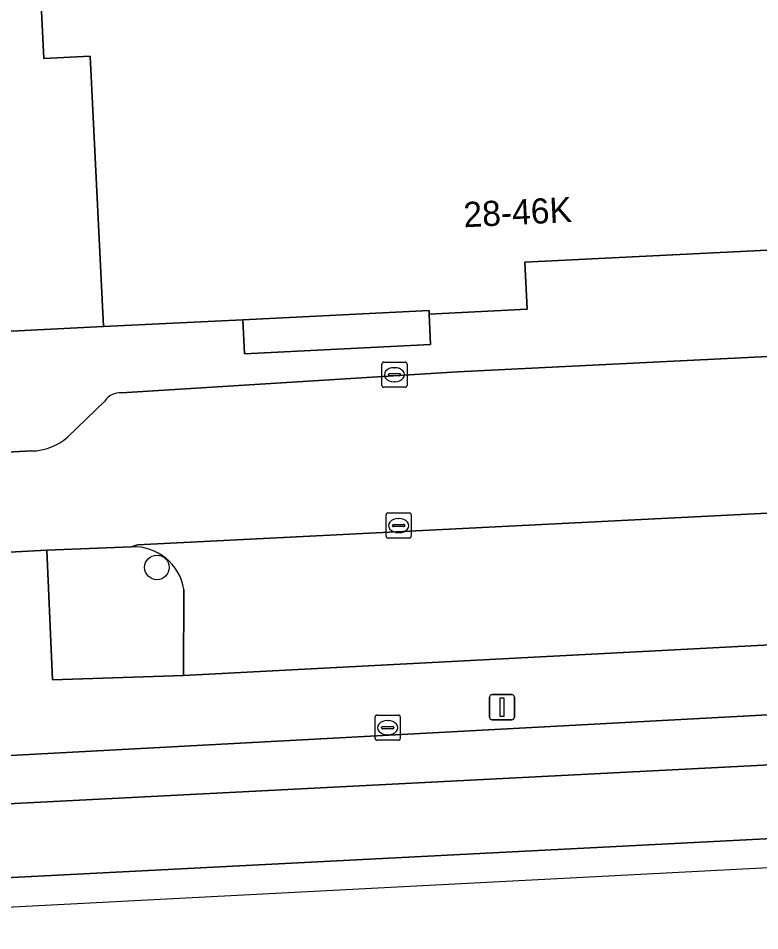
# Model space of a CAD drawing. Extents: x 161084 to 161928, y 385354 to 386522.
# Drawn here: x 161404.59 to 161434.06, y 385358.07 to 385394.35 of the extents above; entities that cross this region are included whole.
import ezdxf

# ---------------------------------------------------------------- set-up
doc = ezdxf.new("R2010")
doc.units = 0
for name, color, linetype in [('IMGEO_Berm_groen', 7, 'Continuous'), ('IMGEO_Boom', 7, 'Continuous'), ('IMGEO_Erf', 7, 'Continuous'), ('IMGEO_Kolk', 7, 'Continuous'), ('IMGEO_Lichtmast', 7, 'Continuous'), ('IMGEO_Pand', 7, 'Continuous'), ('IMGEO_Pand_nummerreeks', 7, 'Continuous'), ('IMGEO_Parkeervlak_open', 7, 'Continuous'), ('IMGEO_Rijbaan_lokaal_gesloten', 7, 'Continuous'), ('IMGEO_Rijbaan_lokaal_open', 7, 'Continuous'), ('IMGEO_Voetpad_open', 7, 'Continuous')]:
    doc.layers.add(name, color=color, linetype=linetype)

msp = doc.modelspace()

# ---------------------------------------------------------------- linework, layer by layer
at = {"layer": 'IMGEO_Berm_groen'}
msp.add_lwpolyline([(161409.084, 385373.337), (161405.722, 385373.199), (161405.948, 385368.052), (161411.152, 385368.227), (161411.169, 385371.645)], dxfattribs=at)
msp.add_arc((161409.17, 385371.312), 2.027, 9.4523, 92.4283, dxfattribs=at)
at = {"layer": 'IMGEO_Boom'}
msp.add_circle((161410.097, 385372.519), 0.489, dxfattribs=at)
at = {"layer": 'IMGEO_Erf'}
msp.add_lwpolyline([(161407.443, 385392.844), (161405.607, 385392.753), (161405.035, 385404.251), (161400.922, 385404.035), (161400.936, 385403.637), (161401.439, 385392.564), (161401.928, 385381.791), (161407.978, 385382.092)], close=True, dxfattribs=at)
at = {"layer": 'IMGEO_Kolk'}
for p, q in [((161419.038, 385379.753), (161419.038, 385380.605)), ((161419.113, 385380.679), (161419.965, 385380.679)), ((161419.526, 385380.459), (161419.551, 385380.459)), ((161420.039, 385380.605), (161420.039, 385379.753)), ((161419.297, 385380.173), (161419.297, 385380.185)), ((161419.735, 385380.136), (161419.337, 385380.136)), ((161419.34, 385380.222), (161419.738, 385380.222)), ((161419.781, 385380.185), (161419.781, 385380.173)), ((161419.965, 385379.679), (161419.113, 385379.679)), ((161419.549, 385379.899), (161419.524, 385379.899)), ((161419.205, 385373.756), (161419.205, 385374.608)), ((161419.28, 385374.682), (161420.132, 385374.682)), ((161420.206, 385374.608), (161420.206, 385373.756)), ((161419.464, 385374.176), (161419.464, 385374.188)), ((161419.507, 385374.225), (161419.905, 385374.225)), ((161419.693, 385374.462), (161419.718, 385374.462)), ((161419.948, 385374.188), (161419.948, 385374.176)), ((161419.902, 385374.139), (161419.504, 385374.139)), ((161419.716, 385373.902), (161419.691, 385373.902)), ((161420.132, 385373.682), (161419.28, 385373.682)), ((161418.772, 385365.721), (161418.772, 385366.573)), ((161418.847, 385366.647), (161419.699, 385366.647)), ((161419.773, 385366.573), (161419.773, 385365.721)), ((161419.26, 385366.427), (161419.285, 385366.427)), ((161419.031, 385366.141), (161419.031, 385366.153)), ((161419.469, 385366.104), (161419.071, 385366.104)), ((161419.074, 385366.19), (161419.472, 385366.19)), ((161419.283, 385365.867), (161419.258, 385365.867)), ((161419.515, 385366.153), (161419.515, 385366.141)), ((161419.699, 385365.647), (161418.847, 385365.647))]:
    msp.add_line(p, q, dxfattribs=at)
for points in [[(161419.038, 385379.753), (161419.038, 385380.605)], [(161419.113, 385380.679), (161419.965, 385380.679)], [(161420.039, 385380.605), (161420.039, 385379.753)], [(161419.965, 385379.679), (161419.113, 385379.679)], [(161419.205, 385373.756), (161419.205, 385374.608)], [(161419.28, 385374.682), (161420.132, 385374.682)], [(161420.206, 385374.608), (161420.206, 385373.756)], [(161420.132, 385373.682), (161419.28, 385373.682)], [(161418.772, 385365.721), (161418.772, 385366.573)], [(161418.847, 385366.647), (161419.699, 385366.647)], [(161419.773, 385366.573), (161419.773, 385365.721)], [(161419.699, 385365.647), (161418.847, 385365.647)]]:
    msp.add_lwpolyline(points, dxfattribs=at)
for centre, radius, start, end in [((161419.115, 385380.603), 0.0765, 91.552, 178.448), ((161419.115, 385380.603), 0.0765, 91.552, 178.448), ((161419.963, 385380.603), 0.0765, 1.552, 88.448), ((161419.963, 385380.603), 0.0765, 1.552, 88.448), ((161419.337, 385380.182), 0.0403, 85.8775, 175.7526), ((161419.334, 385380.172), 0.0366, 178.938, 274.7102), ((161419.738, 385380.179), 0.043, 264.8664, 352.4533), ((161419.742, 385380.184), 0.0386, 1.7309, 96.639), ((161419.115, 385379.755), 0.0765, 181.552, 268.448), ((161419.115, 385379.755), 0.0765, 181.552, 268.448), ((161419.963, 385379.755), 0.0765, 271.552, 358.448), ((161419.963, 385379.755), 0.0765, 271.552, 358.448), ((161419.282, 385374.606), 0.0765, 91.552, 178.448), ((161419.282, 385374.606), 0.0765, 91.552, 178.448), ((161420.13, 385374.606), 0.0765, 1.552, 88.448), ((161420.13, 385374.606), 0.0765, 1.552, 88.448), ((161419.504, 385374.185), 0.0403, 85.8775, 175.7526), ((161419.909, 385374.187), 0.0386, 1.7309, 96.639), ((161419.501, 385374.175), 0.0366, 178.938, 274.7102), ((161419.905, 385374.182), 0.043, 264.8664, 352.4533), ((161419.282, 385373.758), 0.0765, 181.552, 268.448), ((161419.282, 385373.758), 0.0765, 181.552, 268.448), ((161420.13, 385373.758), 0.0765, 271.552, 358.448), ((161420.13, 385373.758), 0.0765, 271.552, 358.448), ((161418.849, 385366.571), 0.0765, 91.552, 178.448), ((161418.849, 385366.571), 0.0765, 91.552, 178.448), ((161419.697, 385366.571), 0.0765, 1.552, 88.448), ((161419.697, 385366.571), 0.0765, 1.552, 88.448), ((161419.071, 385366.15), 0.0403, 85.8775, 175.7526), ((161419.068, 385366.14), 0.0366, 178.938, 274.7102), ((161419.472, 385366.147), 0.043, 264.8664, 352.4533), ((161419.476, 385366.152), 0.0386, 1.7309, 96.639), ((161418.849, 385365.723), 0.0765, 181.552, 268.448), ((161418.849, 385365.723), 0.0765, 181.552, 268.448), ((161419.697, 385365.723), 0.0765, 271.552, 358.448), ((161419.697, 385365.723), 0.0765, 271.552, 358.448)]:
    msp.add_arc(centre, radius, start, end, dxfattribs=at)
for centre, major_axis, ratio, start_param, end_param in [((161419.525, 385380.179), (-0.387, 0.002), 0.722429, 4.712389, 7.853982), ((161419.55, 385380.179), (-0.39, 0.002), 0.717154, 1.570796, 4.712389), ((161419.692, 385374.182), (-0.387, 0.002), 0.722429, 4.712389, 7.853982), ((161419.717, 385374.182), (-0.39, 0.002), 0.717154, 1.570796, 4.712389), ((161419.259, 385366.147), (-0.387, 0.002), 0.722429, 4.712389, 7.853982), ((161419.284, 385366.147), (-0.39, 0.002), 0.717154, 1.570796, 4.712389)]:
    msp.add_ellipse(centre, major_axis=major_axis, ratio=ratio, start_param=start_param, end_param=end_param, dxfattribs=at)
at = {"layer": 'IMGEO_Lichtmast'}
for p, q in [((161423.317, 385366.56), (161423.317, 385367.36)), ((161423.317, 385367.36), (161423.317, 385366.56)), ((161423.417, 385367.46), (161424.207, 385367.46)), ((161424.207, 385367.46), (161423.417, 385367.46)), ((161424.307, 385367.36), (161424.307, 385366.56)), ((161424.307, 385366.56), (161424.307, 385367.36)), ((161424.207, 385366.46), (161423.417, 385366.46)), ((161423.417, 385366.46), (161424.207, 385366.46))]:
    msp.add_line(p, q, dxfattribs=at)
msp.add_lwpolyline([(161423.737, 385367.335), (161423.887, 385367.335), (161423.887, 385366.585), (161423.737, 385366.585), (161423.737, 385367.335)], dxfattribs=at)
for centre, start, end in [((161423.417, 385367.36), 90, 180), ((161423.417, 385367.36), 90, 180), ((161424.207, 385367.36), 0, 90), ((161424.207, 385367.36), 360, 90), ((161423.417, 385366.56), 180, 270), ((161423.417, 385366.56), 180, 270), ((161424.207, 385366.56), 270, 0), ((161424.207, 385366.56), 270, 0)]:
    msp.add_arc(centre, 0.1, start, end, dxfattribs=at)
at = {"layer": 'IMGEO_Pand'}
msp.add_lwpolyline([(161445.572, 385399.025), (161442.544, 385398.875), (161442.426, 385401.249), (161440.171, 385401.137), (161440.017, 385404.225), (161423.461, 385403.401), (161418.467, 385403.152), (161418.379, 385404.916), (161405.035, 385404.251), (161405.607, 385392.753), (161407.443, 385392.844), (161407.978, 385382.092), (161413.514, 385382.368), (161420.918, 385382.736), (161420.925, 385382.589), (161424.817, 385382.783), (161424.724, 385384.657), (161439.175, 385385.376), (161440.478, 385385.441), (161440.573, 385383.548), (161445.352, 385383.786), (161446.313, 385383.833)], close=True, dxfattribs=at)
at = {"layer": 'IMGEO_Parkeervlak_open'}
for points in [[(161613.107, 385383.789), (161536.651, 385379.888), (161500, 385377.979), (161409.328, 385373.422), (161409.084, 385373.337)], [(161411.169, 385371.645), (161411.152, 385368.227), (161436.244, 385369.529), (161499.966, 385372.793), (161536.947, 385374.696), (161611.734, 385378.546)]]:
    msp.add_lwpolyline(points, dxfattribs=at)
msp.add_arc((161409.17, 385371.312), 2.027, 9.4523, 92.4283, dxfattribs=at)
at = {"layer": 'IMGEO_Rijbaan_lokaal_gesloten'}
for points in [[(161625.701, 385371.623), (161625.454, 385376.07), (161622.465, 385375.567), (161622.181, 385375.572), (161615.993, 385374.116), (161611.842, 385373.703), (161604.686, 385373.29), (161508.768, 385368.474), (161402.097, 385363.009), (161402.264, 385360.078), (161479.217, 385364.029), (161505.666, 385365.356), (161523.978, 385366.275), (161544.274, 385367.294), (161580.676, 385369.12), (161602.822, 385370.279), (161621.627, 385370.918)], [(161402.333, 385358.921), (161450.189, 385361.402), (161611.523, 385369.168), (161621.627, 385370.918), (161602.822, 385370.279), (161580.676, 385369.12), (161544.274, 385367.294), (161523.978, 385366.275), (161505.666, 385365.356), (161479.217, 385364.029), (161402.264, 385360.078)]]:
    msp.add_lwpolyline(points, close=True, dxfattribs=at)
for points in [[(161508.768, 385368.474), (161604.686, 385373.29), (161611.842, 385373.703), (161615.993, 385374.116), (161622.181, 385375.572), (161612.776, 385375.763), (161606.577, 385375.444), (161537.172, 385371.897), (161505.307, 385370.314), (161500.052, 385370.04), (161436.355, 385366.757), (161401.799, 385364.905), (161400.42, 385364.894), (161400.333, 385364.8), (161381.454, 385363.768), (161381.262, 385363.858), (161323.951, 385361)], [(161292.857, 385361.465), (161286.612, 385360.011), (161288.172, 385359.529), (161291.222, 385358.909), (161294.158, 385358.451), (161297.736, 385358.198), (161302.025, 385358.107), (161303.986, 385358.072), (161307.966, 385358.21), (161314.892, 385358.542), (161402.097, 385363.009), (161508.768, 385368.474)]]:
    msp.add_lwpolyline(points, dxfattribs=at)
at = {"layer": 'IMGEO_Rijbaan_lokaal_open'}
for points in [[(161503.842, 385384.114), (161501.355, 385384.05), (161500, 385384.027), (161446.746, 385381.511), (161422.04, 385380.3), (161408.687, 385379.455)], [(161396.971, 385372.736), (161405.722, 385373.199), (161409.084, 385373.337), (161409.328, 385373.422), (161500, 385377.979), (161536.651, 385379.888), (161613.107, 385383.789)], [(161408.022, 385379.129), (161406.548, 385377.702)], [(161405.118, 385377.148), (161400.092, 385376.877)]]:
    msp.add_lwpolyline(points, dxfattribs=at)
for centre, radius, start, end in [((161408.625, 385378.74), 0.718, 85.0618, 147.1687), ((161405.097, 385379.325), 2.177, 270.5557, 311.7983)]:
    msp.add_arc(centre, radius, start, end, dxfattribs=at)
at = {"layer": 'IMGEO_Voetpad_open'}
for points in [[(161587.959, 385391.187), (161551.355, 385389.153), (161536.102, 385388.365), (161509.685, 385387), (161504.075, 385386.651), (161500, 385386.452), (161446.313, 385383.833), (161445.352, 385383.786), (161440.573, 385383.548), (161440.478, 385385.441), (161439.175, 385385.376), (161424.724, 385384.657), (161424.817, 385382.783), (161420.925, 385382.589), (161420.977, 385381.375), (161413.582, 385381.007), (161413.514, 385382.368), (161407.978, 385382.092), (161401.928, 385381.791), (161400.092, 385376.877), (161405.118, 385377.148)], [(161408.687, 385379.455), (161422.04, 385380.3), (161446.746, 385381.511), (161500, 385384.027)], [(161406.548, 385377.702), (161408.022, 385379.129)], [(161394.227, 385370.198), (161401.454, 385370.334), (161401.799, 385364.905), (161436.355, 385366.757), (161436.244, 385369.529), (161411.152, 385368.227), (161405.948, 385368.052), (161405.722, 385373.199)], [(161405.722, 385373.199), (161396.971, 385372.736)]]:
    msp.add_lwpolyline(points, dxfattribs=at)
msp.add_lwpolyline([(161413.582, 385381.007), (161420.977, 385381.375), (161420.925, 385382.589), (161420.918, 385382.736), (161413.514, 385382.368)], close=True, dxfattribs=at)
for centre, radius, start, end in [((161408.625, 385378.74), 0.718, 85.0618, 147.1687), ((161405.097, 385379.325), 2.177, 270.5557, 311.7983)]:
    msp.add_arc(centre, radius, start, end, dxfattribs=at)

# ---------------------------------------------------------------- texts
at = {"layer": 'IMGEO_Pand_nummerreeks'}
msp.add_text('28-46K', height=1, rotation=2.8476, dxfattribs=at).set_placement((161422.307, 385386.039))

doc.saveas('drawing.dxf')
